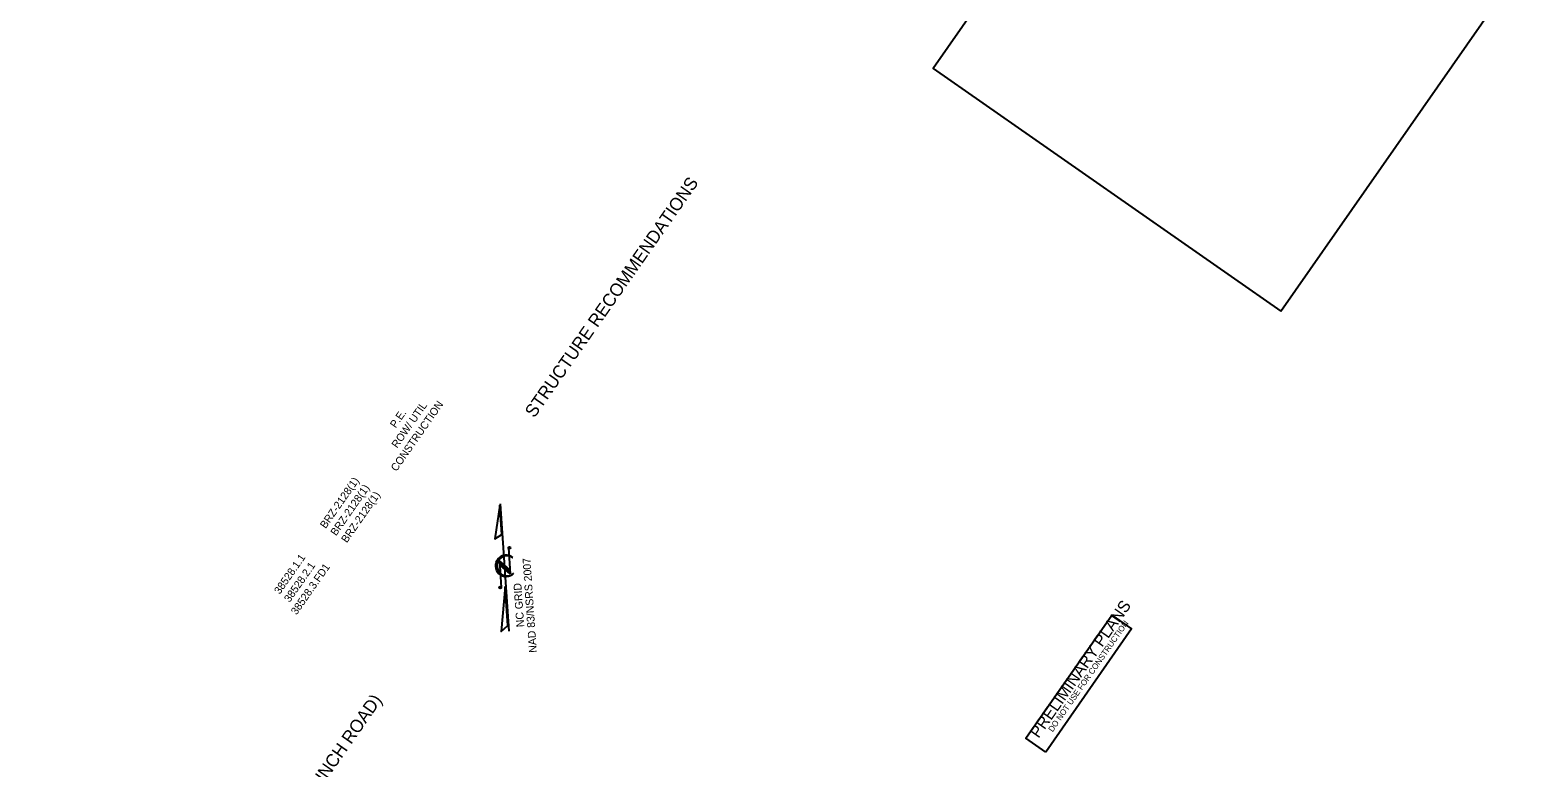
# Model space of a CAD drawing. Extents: x 1731327 to 1735374, y 884856 to 889832.
# Drawn here: x 1731756 to 1733232, y 886088 to 886810 of the extents above; entities that cross this region are included whole.
import ezdxf

# ---------------------------------------------------------------- set-up
doc = ezdxf.new("R2010")
doc.units = 0
for name, color, linetype in [('Exist Horizontal Baseline Alignment Station Label', 7, 'Continuous'), ('Exist Hydro River Flow Arrow CELL', 7, 'Continuous'), ('Exist Structure Minor Pipes RCP 24 Inch', 7, 'Continuous'), ('Exist Vegetation Shrub CELL', 7, 'Continuous')]:
    doc.layers.add(name, color=color, linetype=linetype)

msp = doc.modelspace()

# ---------------------------------------------------------------- linework, layer by layer
at = {"layer": 'Exist Hydro River Flow Arrow CELL'}
msp.add_lwpolyline([(1732750.1, 886103.6), (1732730.8, 886117.1), (1732815, 886237.6), (1732834.2, 886224.2)], close=True, dxfattribs=at)
at = {"layer": 'Exist Structure Minor Pipes RCP 24 Inch'}
msp.add_lwpolyline([(1732980.3, 886535.2), (1733231.7, 886895.6), (1732891.5, 887133), (1732640.1, 886772.6)], close=True, dxfattribs=at)
at = {"layer": 'Exist Vegetation Shrub CELL'}
for p, q in [((1732225.2, 886222.1), (1732216.6, 886346.4)), ((1732224.3, 886303.4), (1732226.1, 886277.9)), ((1732228.5, 886294.2), (1732228.6, 886294.1)), ((1732225.8, 886281.9), (1732215.6, 886290.7)), ((1732215.6, 886290.7), (1732217.4, 886264.8)), ((1732225.8, 886281), (1732215.7, 886289.8)), ((1732215.7, 886289.8), (1732215.8, 886287.5)), ((1732226, 886278.6), (1732215.8, 886287.5)), ((1732215.8, 886287.5), (1732226, 886278.6)), ((1732226.1, 886277.9), (1732215.9, 886286.8)), ((1732226, 886278.6), (1732225.8, 886281))]:
    msp.add_line(p, q, dxfattribs=at)
for points in [[(1732215.8, 886345.2), (1732211, 886312.4), (1732217.8, 886316.5)], [(1732221.2, 886265.8), (1732217.2, 886221.5), (1732223.8, 886227.5)]]:
    msp.add_lwpolyline(points, close=True, dxfattribs=at)
for centre in [(1732225.3, 886303.5), (1732216.4, 886264.7)]:
    msp.add_circle(centre, 1.02, dxfattribs=at)
for centre, radius, start, end in [((1732222.1, 886285.9), 10.5, 51.7867, 316.3407), ((1732223.1, 886285.9), 9.81, 57.0417, 312.5754)]:
    msp.add_arc(centre, radius, start, end, dxfattribs=at)

# ---------------------------------------------------------------- texts
at = {"layer": 'Exist Horizontal Baseline Alignment Station Label'}
for s, height, p in [('STRUCTURE RECOMMENDATIONS', 12.5, (1732249.8, 886430)), ('ROW/ UTIL', 7.5, (1732115.5, 886400.5)), ('CONSTRUCTION', 7.5, (1732114.8, 886377.7)), ('P.E.', 7.5, (1732114, 886420.2)), ('BRZ-2128(1)', 7.5, (1732045.5, 886321.8)), ('BRZ-2128(1)', 7.5, (1732055.7, 886314.7)), ('BRZ-2128(1)', 7.5, (1732066.2, 886307.8)), ('38528.1.1', 7.5, (1732000.6, 886257.5)), ('38528.2.1', 7.5, (1732010.3, 886249.6)), ('38528.3.FD1', 7.5, (1732017, 886237.3)), ('BRIDGE NO. 120 OVER REEDY FORK CREEK ON SR 2128 (BUNCH ROAD)', 12.5, (1731765.8, 885674))]:
    msp.add_text(s, height=height, rotation=55.0911, dxfattribs=at).set_placement(p)
at = {"layer": 'Exist Hydro River Flow Arrow CELL'}
for s, height, p in [('PRELIMINARY PLANS', 11.52, (1732743.1, 886116.5)), ('DO NOT USE FOR CONSTRUCTION', 5.76, (1732756.9, 886122.8))]:
    msp.add_text(s, height=height, rotation=55.0911, dxfattribs=at).set_placement(p)
at = {"layer": 'Exist Vegetation Shrub CELL'}
for s, height, p in [('NAD 83/NSRS 2007', 7.668, (1732252.2, 886201.1)), ('NC GRID', 7.67, (1732239.9, 886226.1))]:
    msp.add_text(s, height=height, rotation=93.9467, dxfattribs=at).set_placement(p)

doc.saveas('drawing.dxf')
